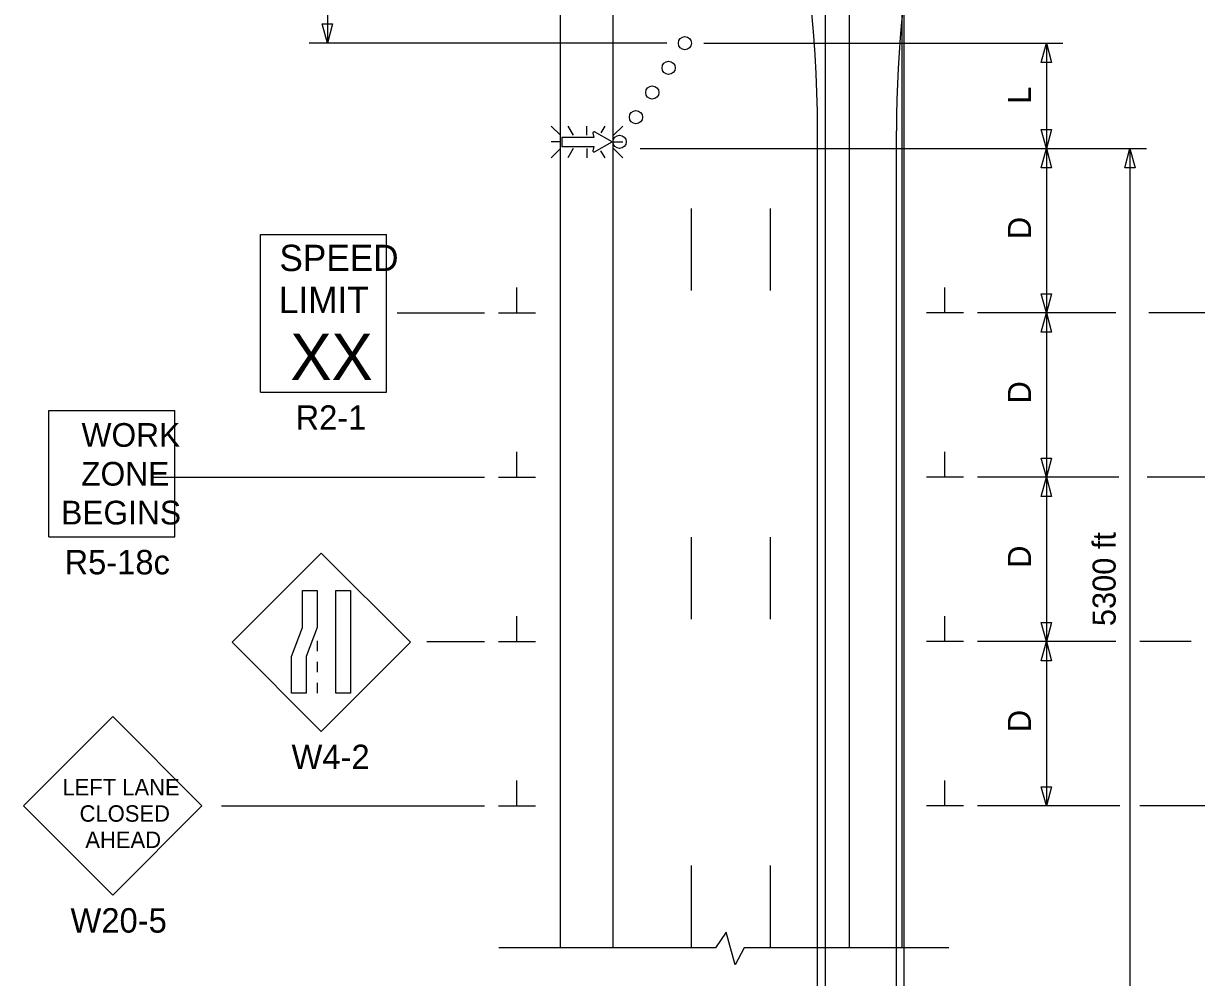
# Model space of a CAD drawing. Extents: x 16476 to 18475, y 6827 to 8243.
# Drawn here: x 16752 to 17109, y 7546.1 to 7836.4 of the extents above; entities that cross this region are included whole.
import ezdxf

# ---------------------------------------------------------------- set-up
doc = ezdxf.new("R2010")
doc.units = 0
for name, color, linetype in [('ALI_LEGAL_EX', 7, 'Continuous'), ('PAVT_EDGE_EX', 7, 'Continuous'), ('TRAFFIC_SIGNS_PR', 7, 'Continuous'), ('TYPICAL_TEXT_DIMEN_PR', 7, 'Continuous')]:
    doc.layers.add(name, color=color, linetype=linetype)

msp = doc.modelspace()

# ---------------------------------------------------------------- linework, layer by layer
at = {"layer": 'ALI_LEGAL_EX'}
for p, q in [((16995.95, 8243.16), (16995.95, 7425.02)), ((17019.95, 8243.16), (17019.95, 7425.02)), ((16993.65, 7303.41), (16993.65, 7803.75)), ((17017.65, 7303.41), (17017.65, 7803.75))]:
    msp.add_line(p, q, dxfattribs=at)
for points in [[(16955.32, 7755.12), (16955.32, 7780.12)], [(16979.32, 7755.12), (16979.32, 7780.12)], [(16955.32, 7655.12), (16955.32, 7680.12)], [(16979.32, 7655.12), (16979.32, 7680.12)], [(16955.32, 7555.12), (16955.32, 7580.12)], [(16979.32, 7555.12), (16979.32, 7580.12)]]:
    msp.add_lwpolyline(points, dxfattribs=at)
for centre, radius, start, end in [((16629.65, 7803.75), 364, 0, 57.2958), ((17357.65, 7803.75), 340, 129.5666, 180)]:
    msp.add_arc(centre, radius, start, end, dxfattribs=at)
at = {"layer": 'PAVT_EDGE_EX'}
for p, q in [((16915.32, 7853.94), (16915.32, 7555.12)), ((16931.32, 7853.94), (16931.32, 7555.12)), ((17003.32, 7853.94), (17003.32, 7555.12)), ((17019.32, 7853.94), (17019.32, 7555.12))]:
    msp.add_line(p, q, dxfattribs=at)
at = {"layer": 'TRAFFIC_SIGNS_PR'}
for p, q in [((16915.39, 7802.35), (16912.56, 7805.17)), ((16917.68, 7805.17), (16919.31, 7802.35)), ((16923.47, 7802.35), (16923.47, 7805.17)), ((16928.94, 7805.17), (16927.73, 7803.07)), ((16934.38, 7805.16), (16931.56, 7802.35)), ((16915.39, 7800.32), (16912.56, 7800.32)), ((16915.39, 7798.28), (16912.56, 7795.46)), ((16919.34, 7798.28), (16917.71, 7795.46)), ((16923.47, 7798.28), (16923.47, 7795.46)), ((16927.65, 7797.65), (16928.92, 7795.46)), ((16931.56, 7800.32), (16934.38, 7800.32)), ((16934.38, 7795.47), (16931.56, 7798.28)), ((16824.13, 7772.18), (16862.53, 7772.18)), ((16824.13, 7724.18), (16824.13, 7772.18)), ((16862.53, 7724.18), (16862.53, 7772.18)), ((16824.13, 7724.18), (16862.53, 7724.18)), ((16759.68, 7680.19), (16759.68, 7718.59)), ((16759.68, 7718.59), (16798.08, 7718.59)), ((16798.08, 7680.19), (16798.08, 7718.59)), ((16759.68, 7680.19), (16798.08, 7680.19)), ((16842.62, 7675.23), (16815.47, 7648.08)), ((16869.78, 7648.08), (16842.62, 7675.23)), ((16815.47, 7648.08), (16842.62, 7620.92)), ((16841.38, 7648.57), (16841.38, 7645.37)), ((16842.62, 7620.92), (16869.78, 7648.08)), ((16841.38, 7642.17), (16841.38, 7638.97)), ((16841.38, 7635.77), (16841.38, 7632.57)), ((16779.15, 7625.49), (16752, 7598.34)), ((16806.31, 7598.34), (16779.15, 7625.49)), ((16752, 7598.34), (16779.15, 7571.18)), ((16779.15, 7571.18), (16806.31, 7598.34))]:
    msp.add_line(p, q, dxfattribs=at)
for points in [[(16925.3, 7803), (16925.53, 7801.7), (16915.81, 7801.7), (16915.81, 7798.96), (16925.53, 7798.96), (16925.3, 7797.65)], [(16925.8, 7797.3), (16931.11, 7800.32), (16925.8, 7803.36)]]:
    msp.add_lwpolyline(points, dxfattribs=at)
for points in [[(16841.38, 7663.81), (16841.38, 7652.63), (16838.03, 7643.75), (16838.03, 7632.57), (16833.54, 7632.57), (16833.54, 7643.75), (16836.88, 7652.63), (16836.88, 7663.81)], [(16851.51, 7663.81), (16851.51, 7632.57), (16847.02, 7632.57), (16847.02, 7663.81)]]:
    msp.add_lwpolyline(points, close=True, dxfattribs=at)
for centre in [(16953.3, 7830.38), (16953.3, 7830.38), (16948.34, 7822.87), (16943.37, 7815.37), (16938.4, 7807.86), (16933.43, 7800.36)]:
    msp.add_circle(centre, 2, dxfattribs=at)
for centre, start, end in [((16925.63, 7803.06), 61.4833, 189.9593), ((16925.63, 7797.6), 170.7308, 298.8916)]:
    msp.add_arc(centre, 0.341, start, end, dxfattribs=at)
at = {"layer": 'TYPICAL_TEXT_DIMEN_PR'}
for p, q in [((16844.49, 7853.94), (16844.49, 7830.38)), ((16844.49, 7830.38), (16842.92, 7836.24)), ((16842.92, 7836.24), (16844.49, 7836.24)), ((16844.49, 7836.24), (16846.06, 7836.24)), ((16846.06, 7836.24), (16844.49, 7830.38)), ((16947.82, 7830.38), (16838.95, 7830.38)), ((16959.07, 7830.38), (17068.32, 7830.38)), ((16961.09, 7830.38), (17068.32, 7830.38)), ((17061.75, 7824.52), (17063.32, 7830.38)), ((17063.32, 7830.38), (17063.32, 7798.28)), ((17063.32, 7830.38), (17063.32, 7798.28)), ((17063.32, 7830.38), (17064.89, 7824.52)), ((17063.32, 7824.52), (17061.75, 7824.52)), ((17064.89, 7824.52), (17063.32, 7824.52)), ((17063.32, 7798.28), (17061.75, 7804.14)), ((17061.75, 7804.14), (17063.32, 7804.14)), ((17063.32, 7804.14), (17064.89, 7804.14)), ((17064.89, 7804.14), (17063.32, 7798.28)), ((16939.71, 7798.28), (17093.75, 7798.28)), ((17061.75, 7792.41), (17063.32, 7798.28)), ((17063.32, 7798.28), (17063.32, 7748.28)), ((17063.32, 7798.28), (17064.89, 7792.41)), ((17087.18, 7792.41), (17088.75, 7798.28)), ((17088.75, 7798.28), (17088.75, 7498.28)), ((17088.75, 7798.28), (17090.32, 7792.41)), ((17063.32, 7792.41), (17061.75, 7792.41)), ((17064.89, 7792.41), (17063.32, 7792.41)), ((17088.75, 7792.41), (17087.18, 7792.41)), ((17090.32, 7792.41), (17088.75, 7792.41)), ((16902.19, 7748.28), (16902.19, 7756.06)), ((16902.19, 7748.28), (16902.19, 7756.06)), ((17032.44, 7748.28), (17032.44, 7756.06)), ((17063.32, 7748.28), (17061.75, 7754.14)), ((17061.75, 7754.14), (17063.32, 7754.14)), ((17063.32, 7754.14), (17064.89, 7754.14)), ((17064.89, 7754.14), (17063.32, 7748.28)), ((16865.75, 7748.28), (16892.32, 7748.28)), ((16866.32, 7748.28), (16892.32, 7748.28)), ((16896.57, 7748.28), (16907.82, 7748.28)), ((16896.57, 7748.28), (16907.82, 7748.28)), ((17038.07, 7748.28), (17026.82, 7748.28)), ((17084.48, 7748.28), (17042.32, 7748.28)), ((17061.75, 7742.41), (17063.32, 7748.28)), ((17063.32, 7748.28), (17064.89, 7742.41)), ((17063.32, 7748.28), (17063.32, 7698.28)), ((17116.65, 7748.28), (17094.47, 7748.28)), ((17063.32, 7742.41), (17061.75, 7742.41)), ((17064.89, 7742.41), (17063.32, 7742.41)), ((16902.19, 7698.28), (16902.19, 7706.06)), ((16902.19, 7698.28), (16902.19, 7706.06)), ((17032.44, 7698.28), (17032.44, 7706.06)), ((17063.32, 7698.28), (17061.75, 7704.14)), ((17061.75, 7704.14), (17063.32, 7704.14)), ((17063.32, 7704.14), (17064.89, 7704.14)), ((17064.89, 7704.14), (17063.32, 7698.28)), ((16790.91, 7698.28), (16892.32, 7698.28)), ((16866.32, 7698.28), (16892.32, 7698.28)), ((16896.57, 7698.28), (16907.82, 7698.28)), ((16896.57, 7698.28), (16907.82, 7698.28)), ((17038.07, 7698.28), (17026.82, 7698.28)), ((17085.39, 7698.28), (17042.32, 7698.28)), ((17061.75, 7692.41), (17063.32, 7698.28)), ((17063.32, 7698.28), (17064.89, 7692.41)), ((17063.32, 7698.28), (17063.32, 7648.28)), ((17164.7, 7698.28), (17094.01, 7698.28)), ((17063.32, 7692.41), (17061.75, 7692.41)), ((17064.89, 7692.41), (17063.32, 7692.41)), ((16902.19, 7648.28), (16902.19, 7656.06)), ((16902.19, 7648.28), (16902.19, 7656.06)), ((17032.44, 7648.28), (17032.44, 7656.06)), ((17063.32, 7648.28), (17061.75, 7654.14)), ((17061.75, 7654.14), (17063.32, 7654.14)), ((17063.32, 7654.14), (17064.89, 7654.14)), ((17064.89, 7654.14), (17063.32, 7648.28)), ((16874.76, 7648.28), (16892.32, 7648.28)), ((16896.57, 7648.28), (16907.82, 7648.28)), ((16896.57, 7648.28), (16907.82, 7648.28)), ((17038.07, 7648.28), (17026.82, 7648.28)), ((17084.48, 7648.28), (17042.32, 7648.28)), ((17061.75, 7642.41), (17063.32, 7648.28)), ((17063.32, 7648.28), (17064.89, 7642.41)), ((17063.32, 7648.28), (17063.32, 7598.28)), ((17107.32, 7648.28), (17091.79, 7648.28)), ((17063.32, 7642.41), (17061.75, 7642.41)), ((17064.89, 7642.41), (17063.32, 7642.41)), ((16902.19, 7598.28), (16902.19, 7606.06)), ((17032.44, 7598.28), (17032.44, 7606.06)), ((17063.32, 7598.28), (17061.75, 7604.14)), ((17061.75, 7604.14), (17063.32, 7604.14)), ((17063.32, 7604.14), (17064.89, 7604.14)), ((17064.89, 7604.14), (17063.32, 7598.28)), ((16812.24, 7598.28), (16892.32, 7598.28)), ((16896.57, 7598.28), (16907.82, 7598.28)), ((17038.07, 7598.28), (17026.82, 7598.28)), ((17085.61, 7598.28), (17042.32, 7598.28)), ((17155.92, 7598.28), (17091.72, 7598.28)), ((16965.83, 7559.92), (16962.57, 7555.12)), ((16968.57, 7549.99), (16965.83, 7559.92)), ((16962.57, 7555.12), (16896.63, 7555.12)), ((16971.31, 7555.12), (16968.57, 7549.99)), ((17033.65, 7555.12), (16971.31, 7555.12))]:
    msp.add_line(p, q, dxfattribs=at)

# ---------------------------------------------------------------- texts
at = {"layer": 'TRAFFIC_SIGNS_PR'}
for s, height, p in [('SPEED', 8, (16829.89, 7761.04)), ('LIMIT', 8, (16829.73, 7748.24)), ('XX', 14.031, (16833.24, 7727.93)), ('R2-1', 7.44, (16834.8, 7712.74)), ('WORK', 7.217, (16769.68, 7707.56)), ('ZONE', 7.217, (16769.56, 7695.75)), ('BEGINS', 7.217, (16763.48, 7683.94)), ('R5-18c', 7.44, (16764.49, 7668.75)), ('W4-2', 7.44, (16833.58, 7609.49)), ('LEFT LANE', 5.001, (16763.85, 7601.49)), ('CLOSED', 5.001, (16769.08, 7593.49)), ('AHEAD', 5.001, (16770.83, 7585.49)), ('W20-5', 7.441, (16766.31, 7559.74))]:
    msp.add_text(s, height=height, dxfattribs=at).set_placement(p)
at = {"layer": 'TYPICAL_TEXT_DIMEN_PR'}
for s, p in [('L', (17058.6, 7811.95)), ('D', (17058.6, 7770.76)), ('D', (17058.6, 7720.76)), ('5300 ft', (17084.38, 7653.01)), ('D', (17058.6, 7670.76)), ('D', (17058.6, 7620.76))]:
    msp.add_text(s, height=7, rotation=90, dxfattribs=at).set_placement(p)

doc.saveas('drawing.dxf')
